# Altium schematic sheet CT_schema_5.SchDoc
size 430 x 414 mm
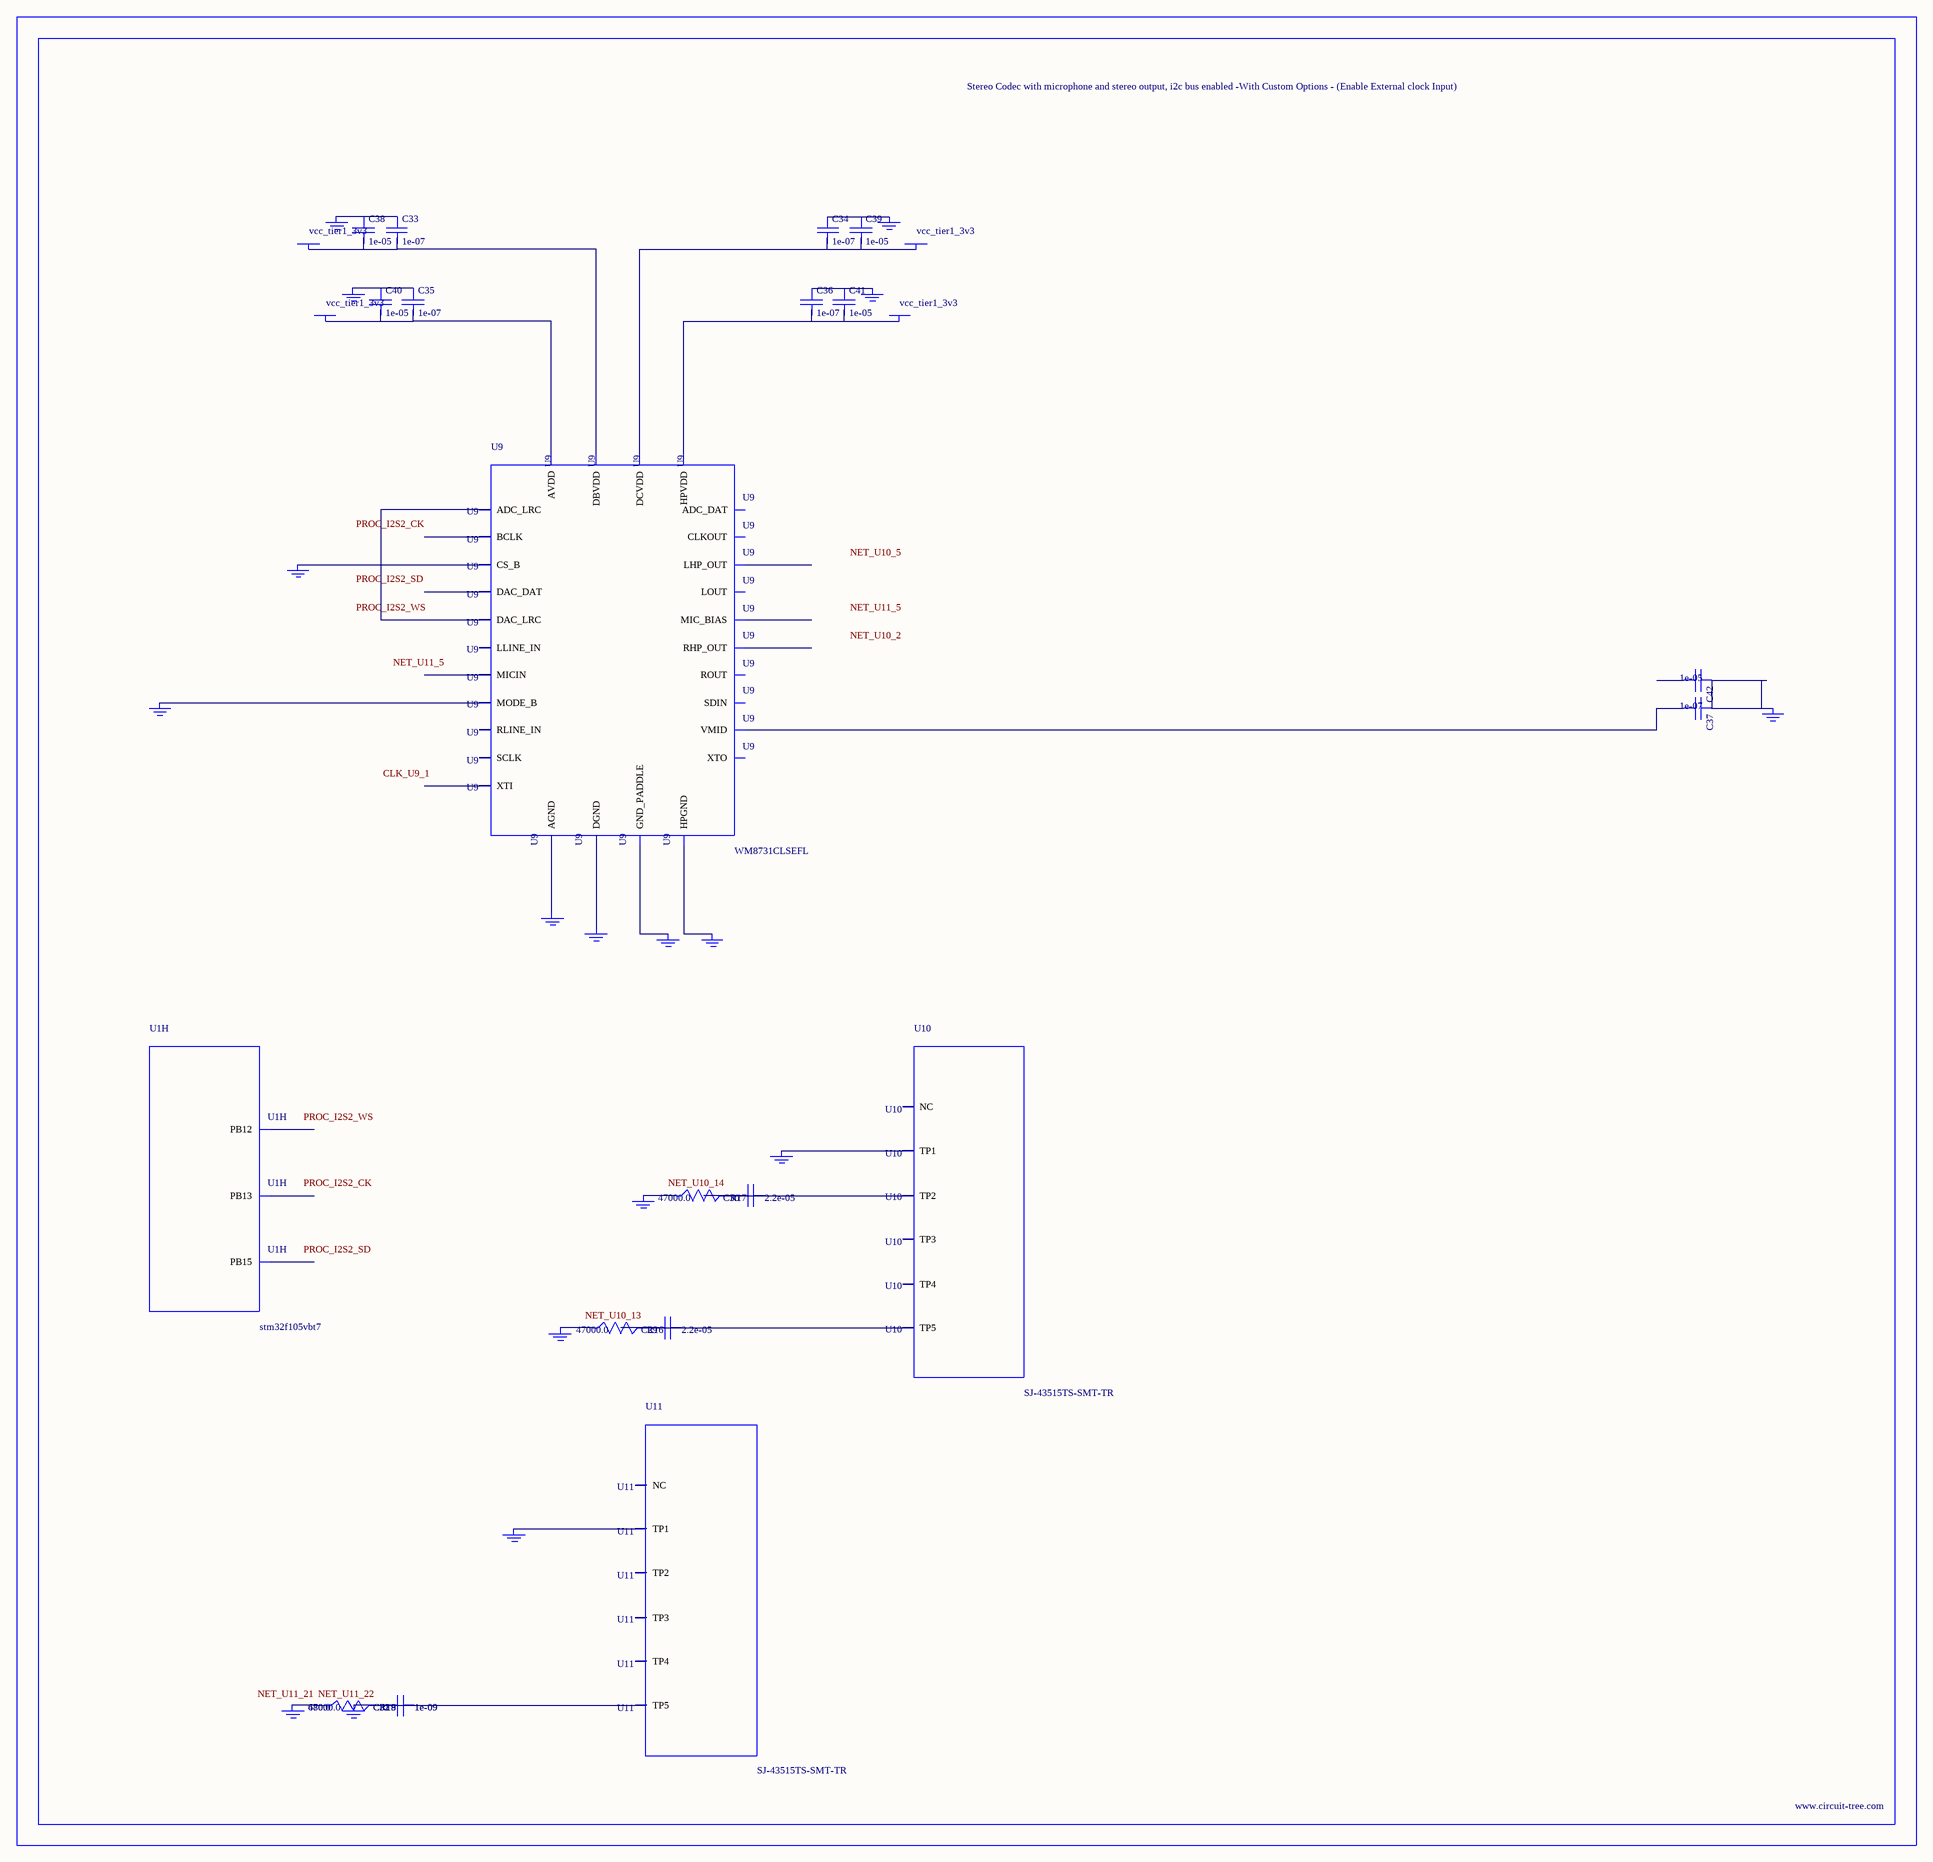
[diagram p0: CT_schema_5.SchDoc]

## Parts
BORDER4  (no value)
C29  2.2e-05  [C1210]
C30  2.2e-05  [C1210]
C31  1e-09  [C0402]
C32  1e-09  [C0402]
C33  1e-07  [C0402]
C34  1e-07  [C0402]
C35  1e-07  [C0402]
C36  1e-07  [C0402]
C37  1e-07  [C0402]
C38  1e-05  [C0805]
C39  1e-05  [C0805]
C40  1e-05  [C0805]
C41  1e-05  [C0805]
C42  1e-05  [C0805]
GND_INSTANCE_4_0  (no value)
GND_INSTANCE_4_1  (no value)
GND_INSTANCE_4_2  (no value)
GND_INSTANCE_4_3  (no value)
GND_INSTANCE_4_4  (no value)
GND_INSTANCE_4_5  (no value)
GND_INSTANCE_4_6  (no value)
GND_INSTANCE_4_7  (no value)
GND_INSTANCE_4_8  (no value)
GND_INSTANCE_4_9  (no value)
GND_INSTANCE_4_10  (no value)
GND_INSTANCE_4_11  (no value)
GND_INSTANCE_4_12  (no value)
GND_INSTANCE_4_13  (no value)
GND_INSTANCE_4_14  (no value)
GND_INSTANCE_4_15  (no value)
GND_INSTANCE_4_16  (no value)
POWER_INSTANCE_4_0  vcc_tier1_3v3
POWER_INSTANCE_4_1  vcc_tier1_3v3
POWER_INSTANCE_4_2  vcc_tier1_3v3
POWER_INSTANCE_4_3  vcc_tier1_3v3
R16  47000.0  [R0603]
R17  47000.0  [R0603]
R18  47000.0  [R0603]
R19  680.0  [R0603]
U1  stm32f105vbt7  [LQFP100]  (part H of 10)
U9  WM8731CLSEFL  [QFN-28]
U10  SJ-43515TS-SMT-TR  [SJ-43515TS-SMT-TR]
U11  SJ-43515TS-SMT-TR  [SJ-43515TS-SMT-TR]

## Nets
NetC29_1: C29.1 C29.2 R16.2 U10.5(TP5)
NetC30_1: C30.1 C30.2 R17.2 U10.2(TP2)
NetC31_1: C31.1 C31.2 C32.1 C32.2 GND_INSTANCE_4_16.0(GND) R18.2 R19.2 U11.5(TP5)
NetC33_1: C33.1 C38.1 GND_INSTANCE_4_1.0(GND)
NetC33_2: C33.2 C38.2 POWER_INSTANCE_4_1.0(PWR) U9.5(DBVDD)
NetC34_1: C34.1 C39.1 GND_INSTANCE_4_0.0(GND)
NetC34_2: C34.2 C39.2 POWER_INSTANCE_4_0.0(PWR) U9.3(DCVDD)
NetC35_1: C35.1 C40.1 GND_INSTANCE_4_4.0(GND)
NetC35_2: C35.2 C40.2 POWER_INSTANCE_4_3.0(PWR) U9.18(AVDD)
NetC36_1: C36.1 C41.1 GND_INSTANCE_4_2.0(GND)
NetC36_2: C36.2 C41.2 POWER_INSTANCE_4_2.0(PWR) U9.12(HPVDD)
NetC37_1: C37.1 C42.1 GND_INSTANCE_4_5.0(GND)
NetC37_2: C37.2 U9.20(VMID)
NetGND_INSTANCE_4_3_0: GND_INSTANCE_4_3.0(GND) U9.15(HPGND)
NetGND_INSTANCE_4_6_0: GND_INSTANCE_4_6.0(GND) U9.25(MODE_B)
NetGND_INSTANCE_4_7_0: GND_INSTANCE_4_7.0(GND) U9.26(CS_B)
NetGND_INSTANCE_4_8_0: GND_INSTANCE_4_8.0(GND) U9.29(GND_PADDLE)
NetGND_INSTANCE_4_9_0: GND_INSTANCE_4_9.0(GND) U9.4(DGND)
NetGND_INSTANCE_4_10_0: GND_INSTANCE_4_10.0(GND) U9.19(AGND)
NetGND_INSTANCE_4_11_0: GND_INSTANCE_4_11.0(GND) U10.1(TP1)
NetGND_INSTANCE_4_12_0: GND_INSTANCE_4_12.0(GND) R17.1
NetGND_INSTANCE_4_13_0: GND_INSTANCE_4_13.0(GND) R16.1
NetGND_INSTANCE_4_14_0: GND_INSTANCE_4_14.0(GND) U11.1(TP1)
NetGND_INSTANCE_4_15_0: GND_INSTANCE_4_15.0(GND) R18.1 R19.1
NetU9_9: U9.9(DAC_LRC) U9.11(ADC_LRC)

Not connected (* = marked no-connect by the designer): C42 2; U1 51(PB12) 52(PB13) 54(PB15); U9 1(XTI) 2(XTO) 6(CLKOUT) 7(BCLK) 8(DAC_DAT) 10(ADC_DAT) 13(LHP_OUT) 14(RHP_OUT) 16(LOUT) 17(ROUT) 21(MIC_BIAS) 22(MICIN) 23(RLINE_IN) 24(LLINE_IN) 27(SDIN) 28(SCLK); U10 3(TP3) 4(TP4) 6(NC); U11 2(TP2) 3(TP3) 4(TP4) 6(NC)

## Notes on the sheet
- Labels drawn without touching a wire or pin: CLK_U9_1, NET_U10_2, NET_U10_5, NET_U10_13, NET_U10_14, NET_U11_5, NET_U11_21, NET_U11_22, PROC_I2S2_CK, PROC_I2S2_SD, PROC_I2S2_WS

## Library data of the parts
BORDER4 = BORDER_PAGE4
C29 C30 = C1210C224K5RACTU
C31 C32 = C0402C102K3RAC
C33-C37 = C0402C104K3RACTU
C38-C42 = C0805C106K8RACTU
GND_INSTANCE_4_0-GND_INSTANCE_4_16 = GND
POWER_INSTANCE_4_0-POWER_INSTANCE_4_3 = PWR
R16-R18 = RC0603JR-0747KL
R19 = RC0603JR-07680RL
